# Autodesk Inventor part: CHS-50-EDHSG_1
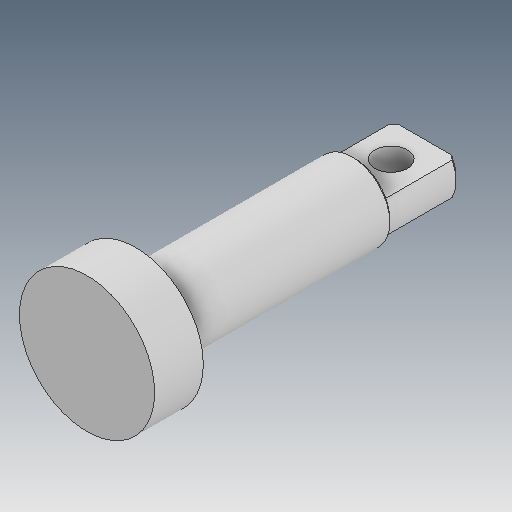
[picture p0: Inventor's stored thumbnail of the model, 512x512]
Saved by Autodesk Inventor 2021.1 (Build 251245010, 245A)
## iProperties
Created: 2019-04
Part Number: CHS-50-EDHSG_1
Material: Ogólny
Document SubType Name: Modeling
Designer: user
Density: 1 g/cm^3
Appearance: Domyślna
Author: user
Revision Number: ÈÎºÎ
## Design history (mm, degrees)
feature "ÊäÈë1"
node "Bryła1"
